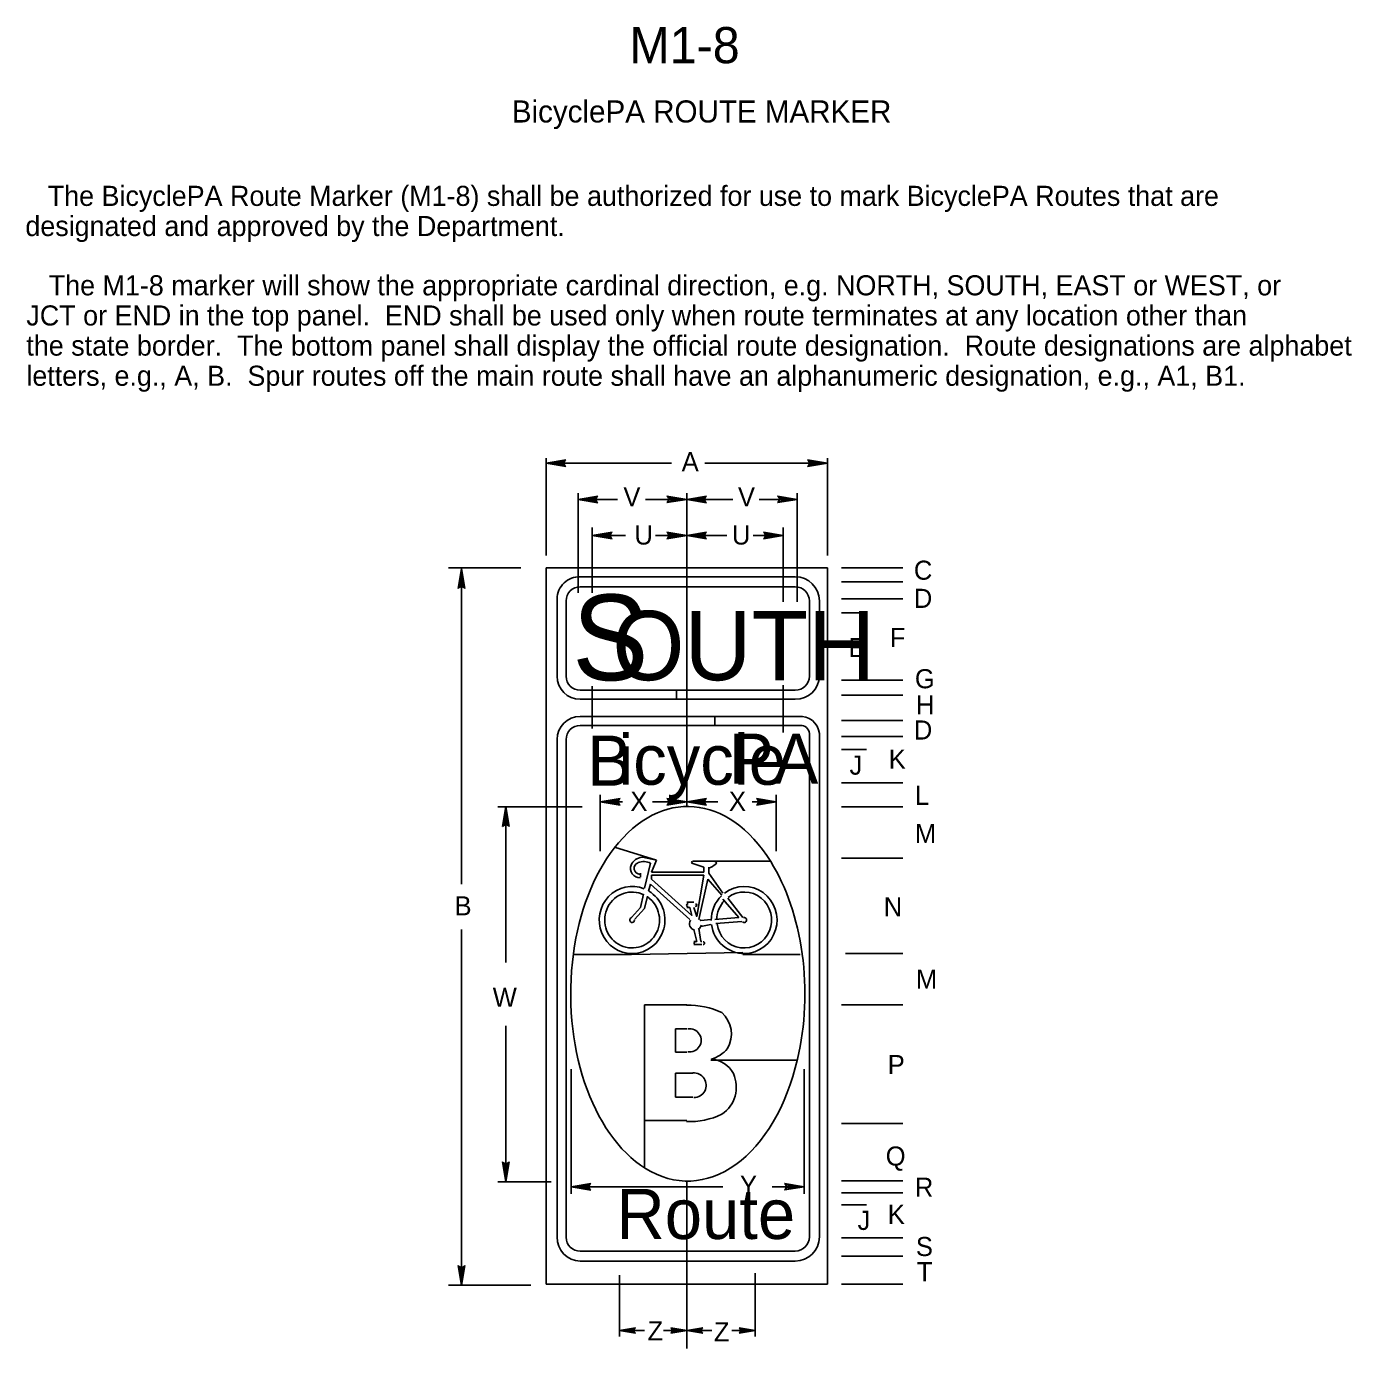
# Model space of a CAD drawing. Extents: x 0.013 to 0.192, y 0.004 to 0.259.
# Drawn here: x 0.0274 to 0.1922, y 0.0948 to 0.2592 of the extents above; entities that cross this region are included whole.
import ezdxf

# ---------------------------------------------------------------- set-up
doc = ezdxf.new("R2010")
doc.units = 0
for name, color, linetype in [('1', 7, 'Continuous'), ('2', 7, 'Continuous'), ('3', 7, 'Continuous')]:
    doc.layers.add(name, color=color, linetype=linetype)

# ---------------------------------------------------------------- blocks, each defined once
blk = doc.blocks.new('RARROW')
at = {"layer": '3'}
for p, q in [((-2.156, 0.28500000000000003), (-2.2665, 0.384625)), ((-2.2665, 0.384625), (0, 0)), ((0, 0), (-2.2665, -0.379125)), ((-2.156, 0.28500000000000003), (-2.075625, 0.12075)), ((0, 0), (-2.156, 0.28500000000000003)), ((-2.14975, -0.2705), (0, 0)), ((-2.075625, 0.12075), (0, 0)), ((0, 0), (-2.074, -0.108)), ((-2.2665, -0.379125), (-2.14975, -0.2705)), ((-2.074, -0.108), (-2.14975, -0.2705))]:
    blk.add_line(p, q, dxfattribs=at)

msp = doc.modelspace()

# ---------------------------------------------------------------- linework, layer by layer
at = {"layer": '3'}
for p, q in [((0.092, 0.193375), (0.092, 0.20550000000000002)), ((0.092, 0.204875), (0.107625, 0.204875)), ((0.11175, 0.204875), (0.127, 0.204875)), ((0.127, 0.193375), (0.127, 0.20550000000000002)), ((0.096, 0.18875), (0.096, 0.201125)), ((0.1095, 0.19425), (0.1095, 0.201125)), ((0.12325, 0.18762500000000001), (0.12325, 0.201125)), ((0.096, 0.200375), (0.100875, 0.200375)), ((0.104375, 0.200375), (0.1095, 0.200375)), ((0.1095, 0.200375), (0.11525, 0.200375)), ((0.11850000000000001, 0.200375), (0.12325, 0.200375)), ((0.09775, 0.18875), (0.09775, 0.196875)), ((0.1215, 0.18762500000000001), (0.1215, 0.196875)), ((0.09775, 0.195875), (0.10187500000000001, 0.195875)), ((0.105625, 0.195875), (0.1095, 0.195875)), ((0.1095, 0.195875), (0.1145, 0.195875)), ((0.11775000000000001, 0.195875), (0.1215, 0.195875)), ((0.1095, 0.162125), (0.1095, 0.19425)), ((0.088875, 0.19187500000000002), (0.079875, 0.19187500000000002)), ((0.0815, 0.1525), (0.0815, 0.19187500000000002)), ((0.127, 0.19187500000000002), (0.092, 0.19187500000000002)), ((0.092, 0.19187500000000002), (0.092, 0.10275000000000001)), ((0.127, 0.19187500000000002), (0.127, 0.10275000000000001)), ((0.12875, 0.19187500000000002), (0.136375, 0.19187500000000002)), ((0.123, 0.19075), (0.09625, 0.19075)), ((0.12875, 0.19012500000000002), (0.136375, 0.19012500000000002)), ((0.093375, 0.188), (0.093375, 0.178375)), ((0.09625, 0.1895), (0.123, 0.1895)), ((0.12875, 0.188), (0.136375, 0.188)), ((0.0945, 0.178375), (0.0945, 0.18775)), ((0.12475, 0.18775), (0.12475, 0.178375)), ((0.126, 0.178375), (0.126, 0.18775)), ((0.12875, 0.18625), (0.131875, 0.18625)), ((0.09775, 0.171875), (0.09775, 0.177125)), ((0.1215, 0.171375), (0.1215, 0.17725)), ((0.12875, 0.177875), (0.136375, 0.177875)), ((0.12875, 0.176), (0.136375, 0.176)), ((0.09625, 0.173375), (0.113, 0.173375)), ((0.12875, 0.172875), (0.136375, 0.172875)), ((0.093375, 0.108625), (0.093375, 0.1705)), ((0.0945, 0.1705), (0.0945, 0.108625)), ((0.12475, 0.108625), (0.12475, 0.17125)), ((0.126, 0.17125), (0.126, 0.108625)), ((0.12875, 0.170875), (0.136375, 0.170875)), ((0.12875, 0.16925), (0.131875, 0.16925)), ((0.12875, 0.165125), (0.136375, 0.165125)), ((0.09875, 0.15662500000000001), (0.09875, 0.163625)), ((0.120625, 0.15662500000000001), (0.120625, 0.163625)), ((0.08600000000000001, 0.162125), (0.0965, 0.162125)), ((0.08700000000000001, 0.14275000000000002), (0.08700000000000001, 0.162125)), ((0.09875, 0.16275), (0.1015, 0.16275)), ((0.10525, 0.16275), (0.1095, 0.16275)), ((0.113375, 0.16275), (0.1095, 0.16275)), ((0.120625, 0.16275), (0.11762500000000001, 0.16275)), ((0.12875, 0.162125), (0.136375, 0.162125)), ((0.10575, 0.1555), (0.1005, 0.15712500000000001)), ((0.1005, 0.15712500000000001), (0.10575, 0.1555)), ((0.1005, 0.15712500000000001), (0.1005, 0.15712500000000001)), ((0.104625, 0.15575), (0.10400000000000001, 0.155875)), ((0.10400000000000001, 0.155875), (0.10575, 0.1555)), ((0.105, 0.155125), (0.10425, 0.152)), ((0.105125, 0.154), (0.10575, 0.1555)), ((0.110125, 0.155125), (0.111625, 0.154625)), ((0.113, 0.155375), (0.11025, 0.155375)), ((0.113, 0.155375), (0.113, 0.155375)), ((0.113, 0.155375), (0.113, 0.155375)), ((0.12, 0.155375), (0.113, 0.155375)), ((0.12, 0.155375), (0.113, 0.155375)), ((0.12875, 0.15575), (0.136375, 0.15575)), ((0.10375000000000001, 0.153375), (0.10375000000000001, 0.153875)), ((0.111625, 0.154), (0.105125, 0.154)), ((0.111625, 0.154625), (0.111625, 0.154)), ((0.11225, 0.154625), (0.11225, 0.153875)), ((0.11225, 0.153875), (0.114, 0.151375)), ((0.105, 0.1525), (0.10475, 0.151625)), ((0.109875, 0.148125), (0.105, 0.1525)), ((0.112125, 0.153125), (0.111, 0.148125)), ((0.113875, 0.151125), (0.112125, 0.153125)), ((0.104125, 0.15125), (0.10375000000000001, 0.149625)), ((0.10425, 0.1495), (0.104625, 0.151)), ((0.104625, 0.151), (0.104625, 0.151)), ((0.110375, 0.15025), (0.1095, 0.15025)), ((0.113875, 0.151125), (0.113875, 0.151125)), ((0.116, 0.148375), (0.114, 0.150625)), ((0.114625, 0.15075), (0.114625, 0.15075)), ((0.114625, 0.15075), (0.1165, 0.148375)), ((0.10375000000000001, 0.149625), (0.10262500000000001, 0.148375)), ((0.10300000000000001, 0.148125), (0.10425, 0.1495)), ((0.113, 0.148125), (0.116, 0.148375)), ((0.0815, 0.10275000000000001), (0.0815, 0.146875)), ((0.109875, 0.148125), (0.109875, 0.148125)), ((0.11075, 0.145375), (0.110375, 0.146875)), ((0.111, 0.147), (0.11125, 0.145375)), ((0.11125, 0.148), (0.1125, 0.148125)), ((0.1125, 0.1475), (0.11125, 0.14725)), ((0.116375, 0.147875), (0.113125, 0.147625)), ((0.113125, 0.147625), (0.113125, 0.147625)), ((0.110375, 0.145375), (0.11075, 0.145375)), ((0.11125, 0.145375), (0.111375, 0.145375)), ((0.10262500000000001, 0.14375000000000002), (0.095375, 0.14375000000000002)), ((0.095375, 0.14375000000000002), (0.10262500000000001, 0.14375000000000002)), ((0.095375, 0.14375000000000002), (0.095375, 0.14375000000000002)), ((0.10262500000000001, 0.14375000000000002), (0.1165, 0.14400000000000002)), ((0.10262500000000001, 0.14375000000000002), (0.1165, 0.14400000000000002)), ((0.111375, 0.145), (0.110375, 0.145)), ((0.1165, 0.14375000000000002), (0.123625, 0.14375000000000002)), ((0.1165, 0.14375000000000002), (0.123625, 0.14375000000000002)), ((0.12925, 0.143875), (0.136375, 0.143875)), ((0.1095, 0.1375), (0.10425, 0.1375)), ((0.10425, 0.1375), (0.10425, 0.11725000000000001)), ((0.12875, 0.1375), (0.136375, 0.1375)), ((0.08700000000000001, 0.115625), (0.08700000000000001, 0.134875)), ((0.108125, 0.131625), (0.108125, 0.1345)), ((0.108125, 0.1345), (0.1095, 0.1345)), ((0.1095, 0.131625), (0.108125, 0.131625)), ((0.12325, 0.130625), (0.1125, 0.130625)), ((0.123, 0.130625), (0.1125, 0.130625)), ((0.12325, 0.130625), (0.123, 0.130625)), ((0.095125, 0.114), (0.095125, 0.1295)), ((0.108125, 0.129), (0.11025, 0.129)), ((0.108125, 0.126), (0.108125, 0.129)), ((0.124125, 0.114), (0.124125, 0.1295)), ((0.11025, 0.126), (0.108125, 0.126)), ((0.1095, 0.123125), (0.10425, 0.123125)), ((0.10425, 0.123125), (0.10425, 0.11725000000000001)), ((0.12875, 0.12275), (0.136375, 0.12275)), ((0.08600000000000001, 0.1155), (0.092625, 0.1155)), ((0.1095, 0.09475), (0.1095, 0.115625)), ((0.12875, 0.115625), (0.136375, 0.115625)), ((0.095125, 0.114875), (0.114, 0.114875)), ((0.120125, 0.114875), (0.124125, 0.114875)), ((0.12875, 0.114125), (0.136375, 0.114125)), ((0.12875, 0.112625), (0.131875, 0.112625)), ((0.12875, 0.1085), (0.136375, 0.1085)), ((0.09625, 0.106875), (0.123, 0.106875)), ((0.123, 0.105625), (0.09625, 0.105625)), ((0.12875, 0.10625), (0.136375, 0.10625)), ((0.101125, 0.09625), (0.101125, 0.10387500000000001)), ((0.11800000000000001, 0.09625), (0.11800000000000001, 0.104125)), ((0.090125, 0.10262500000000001), (0.079875, 0.10262500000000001)), ((0.127, 0.10275000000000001), (0.092, 0.10275000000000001)), ((0.12875, 0.10275000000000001), (0.136375, 0.10275000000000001)), ((0.101125, 0.097), (0.10425, 0.097)), ((0.106625, 0.097), (0.1095, 0.097)), ((0.1095, 0.097), (0.112625, 0.097)), ((0.115125, 0.097), (0.11800000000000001, 0.097))]:
    msp.add_line(p, q, dxfattribs=at)
for points in [[(0.09625, 0.17550000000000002), (0.10825, 0.17550000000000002), (0.10825, 0.176625), (0.09625, 0.176625)], [(0.123, 0.176625), (0.10825, 0.176625), (0.10825, 0.17550000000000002), (0.123, 0.17550000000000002)], [(0.113, 0.173375), (0.113, 0.17225000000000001), (0.09625, 0.17225000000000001)], [(0.123625, 0.17225000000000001), (0.113, 0.17225000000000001), (0.113, 0.173375), (0.123375, 0.173375)], [(0.1095, 0.149625), (0.109875, 0.149625), (0.110125, 0.148625), (0.105125, 0.153125), (0.105125, 0.153625), (0.111625, 0.153625)], [(0.111625, 0.153625), (0.11075, 0.1485), (0.110375, 0.149625), (0.110375, 0.149625)]]:
    msp.add_lwpolyline(points, dxfattribs=at)
for centre, radius, start, end in [((0.09618083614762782, 0.18794446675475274), 0.002806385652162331, 88.58779166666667, 178.86614722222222), ((0.12300000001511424, 0.18775000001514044), 0.002999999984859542, 0, 90), ((0.09624999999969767, 0.1877500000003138), 0.0017499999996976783, 90, 180), ((0.12300000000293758, 0.1877500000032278), 0.0017499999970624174, 0, 90), ((0.09624999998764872, 0.1783749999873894), 0.002874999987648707, 180, 270), ((0.09624999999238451, 0.1783749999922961), 0.0017499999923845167, 180, 270), ((0.12299999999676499, 0.17837500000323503), 0.0017500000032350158, 270, 0), ((0.12306250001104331, 0.1784374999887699), 0.002938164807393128, 268.78112500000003, 358.78112500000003), ((0.09625000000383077, 0.17049999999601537), 0.0028750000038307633, 90, 180), ((0.12362500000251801, 0.1710000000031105), 0.002388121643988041, 6.009005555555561, 96.00900555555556), ((0.09625000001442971, 0.17049999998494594), 0.0017500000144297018, 90, 180), ((0.12368750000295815, 0.1711875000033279), 0.0010643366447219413, 3.366461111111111, 93.36646111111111), ((0.10404730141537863, 0.15425182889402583), 0.0015972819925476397, 93.5801888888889, 156.6766), ((0.10372970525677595, 0.15448047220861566), 0.0007575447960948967, 112.33130277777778, 268.05661388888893), ((0.1041421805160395, 0.15356406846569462), 0.001756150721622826, 60.59737777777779, 112.67573055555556), ((0.10366965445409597, 0.1544696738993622), 0.0011653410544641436, 159.16154444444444, 272.64576666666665), ((0.10976705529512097, 0.12778106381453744), 0.00966476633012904, 64.91580277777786, 91.7117472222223), ((0.11145229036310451, 0.1338557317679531), 0.0036046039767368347, 329.89579722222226, 47.99597777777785), ((0.10986700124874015, 0.13308092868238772), 0.0014274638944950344, 261.5001972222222, 98.49980277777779), ((0.11127861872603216, 0.13490674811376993), 0.004360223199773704, 287.0058444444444, 319.02734722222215), ((0.11233826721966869, 0.1274018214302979), 0.0033423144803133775, 27.545941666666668, 86.30179444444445), ((0.11039280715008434, 0.12749953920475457), 0.001528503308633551, 270.00161944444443, 95.1911), ((0.11159194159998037, 0.12726206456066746), 0.004074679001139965, 303.89755, 24.43358055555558), ((0.10976705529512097, 0.13263317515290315), 0.009664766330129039, 268.2882527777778, 295.08419722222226), ((0.09631250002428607, 0.10856250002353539), 0.002938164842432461, 178.78112500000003, 268.78112500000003), ((0.09622435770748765, 0.1086111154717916), 0.0017363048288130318, 180.84619166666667, 270.84619166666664), ((0.12300000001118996, 0.1086249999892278), 0.0017499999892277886, 270, 0), ((0.12300000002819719, 0.10862499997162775), 0.0029999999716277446, 270, 0)]:
    msp.add_arc(centre, radius, start, end, dxfattribs=at)
for centre, major_axis, ratio, start_param, end_param in [((0.10963271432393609, 0.1388744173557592), (1.4266637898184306e-18, 0.0232991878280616), 0.6249999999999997, 5.495524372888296, 6.964212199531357), ((0.10963271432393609, 0.1388744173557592), (1.4266637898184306e-18, 0.0232991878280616), 0.6249999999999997, 0.6810429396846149, 1.3549990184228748), ((0.11022207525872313, 0.15520128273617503), (6.81501369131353e-21, 0.00011129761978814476), 0.9804052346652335, 0, 2.7964537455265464), ((0.11078883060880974, 0.15808036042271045), (-7.139456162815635e-19, -0.0038865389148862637), 0.9804052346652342, 0.3922214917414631, 0.6561810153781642), ((0.11303251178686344, 0.1551456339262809), (-3.0667561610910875e-20, -0.0001669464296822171), 0.9804052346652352, 0.5182421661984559, 3.141592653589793), ((0.10963271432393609, 0.1388744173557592), (1.4266637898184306e-18, 0.0232991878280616), 0.6249999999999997, 4.927689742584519, 5.4955178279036), ((0.10270776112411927, 0.14805041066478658), (2.5556301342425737e-19, 0.004173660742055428), 0.980405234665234, 5.90428067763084, 9.426492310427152), ((0.10270776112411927, 0.14805041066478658), (2.1296917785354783e-19, 0.003478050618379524), 0.9804052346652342, 5.8372009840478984, 11.962836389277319), ((0.10270776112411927, 0.14805041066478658), (2.5556301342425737e-19, 0.004173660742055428), 0.980405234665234, 3.1432242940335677, 5.749303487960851), ((0.11664618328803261, 0.14805041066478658), (2.1296917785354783e-19, 0.003478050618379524), 0.9804052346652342, 1.7079627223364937, 6.913561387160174), ((0.11664618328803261, 0.14805041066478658), (2.5556301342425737e-19, 0.004173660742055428), 0.980405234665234, 3.1582208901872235, 6.92157007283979), ((0.10965005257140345, 0.14989595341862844), (1.0686641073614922e-20, 0.00017452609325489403), 0.980405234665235, 6.198627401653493, 9.509335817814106), ((0.11058632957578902, 0.14990614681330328), (1.0686641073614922e-20, 0.00017452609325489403), 0.980405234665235, 3.057034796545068, 6.187256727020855), ((0.11664618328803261, 0.14805041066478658), (2.5556301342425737e-19, 0.004173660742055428), 0.980405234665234, 0.7638517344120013, 1.583042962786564), ((0.11664618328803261, 0.14805041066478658), (2.1296917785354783e-19, 0.003478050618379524), 0.9804052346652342, 0.7848713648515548, 1.5684358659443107), ((0.10270776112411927, 0.14805041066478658), (1.8826475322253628e-20, 0.0003074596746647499), 0.9804052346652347, 0.2825696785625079, 4.644742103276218), ((0.11664618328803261, 0.14805041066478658), (1.8826475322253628e-20, 0.0003074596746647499), 0.9804052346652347, 2.3681356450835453, 6.55357316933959), ((0.11058611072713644, 0.14758991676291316), (4.7130035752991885e-20, 0.0007696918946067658), 0.9804052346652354, 0.9898988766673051, 3.006996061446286), ((0.11058611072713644, 0.14758991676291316), (4.7130035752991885e-20, 0.0007696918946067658), 0.9804052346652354, 3.623585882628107, 4.496485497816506), ((0.11058611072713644, 0.14758991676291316), (4.7130035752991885e-20, 0.0007696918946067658), 0.9804052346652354, 5.179197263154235, 5.449443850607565), ((0.11664618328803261, 0.14805041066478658), (2.5556301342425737e-19, 0.004173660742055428), 0.980405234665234, 1.7006056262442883, 3.158212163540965), ((0.11058529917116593, 0.14517754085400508), (1.0686641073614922e-20, 0.00017452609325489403), 0.980405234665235, 6.198627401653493, 9.509335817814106), ((0.11154778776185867, 0.14517754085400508), (1.0686641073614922e-20, 0.00017452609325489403), 0.980405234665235, 3.0570347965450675, 6.36774321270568), ((0.10963271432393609, 0.1388744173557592), (1.4266637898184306e-18, 0.0232991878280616), 0.6249999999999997, 1.3561330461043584, 2.77126399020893), ((0.10963271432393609, 0.1388744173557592), (1.4266637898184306e-18, 0.0232991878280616), 0.6249999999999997, 4.355608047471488, 4.9260615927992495), ((0.10963271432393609, 0.1388744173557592), (1.4266637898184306e-18, 0.0232991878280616), 0.6249999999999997, 2.771276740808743, 4.3556411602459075)]:
    msp.add_ellipse(centre, major_axis=major_axis, ratio=ratio, start_param=start_param, end_param=end_param, dxfattribs=at)

# ---------------------------------------------------------------- block references
for p, xscale, yscale, rotation in [((0.092, 0.204875), 0.0010855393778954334, 0.0010738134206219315, 180), ((0.096, 0.200375), 0.0010855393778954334, 0.0010738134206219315, 180), ((0.1095, 0.200375), 0.0010855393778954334, 0.0010738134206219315, 180), ((0.09775, 0.195875), 0.0010855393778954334, 0.0010738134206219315, 180), ((0.1095, 0.195875), 0.0010855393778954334, 0.0010738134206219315, 180), ((0.0815, 0.19175), 0.0010855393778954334, 0.0010738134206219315, 90), ((0.09875, 0.16275), 0.0010855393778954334, 0.0010738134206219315, 180), ((0.1095, 0.16275), 0.0010855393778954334, 0.0010738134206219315, 180), ((0.08700000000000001, 0.162125), 0.0010855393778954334, 0.0010738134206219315, 90), ((0.08700000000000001, 0.1155), 0.0010855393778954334, 0.0010738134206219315, -90.00000000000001), ((0.095125, 0.114875), 0.0010855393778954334, 0.0010738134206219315, 180), ((0.0815, 0.10262500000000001), 0.0010855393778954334, 0.0010738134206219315, -90.00000000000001), ((0.101125, 0.097), 0.0008792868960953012, 0.0008697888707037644, 180), ((0.1095, 0.097), 0.0008792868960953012, 0.0008697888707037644, 180)]:
    msp.add_blockref('RARROW', p, dxfattribs=dict(at, xscale=xscale, yscale=yscale, rotation=rotation))
for p, xscale, yscale in [((0.127, 0.204875), 0.0010855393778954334, 0.0010738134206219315), ((0.1095, 0.200375), 0.0010855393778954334, 0.0010738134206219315), ((0.12325, 0.200375), 0.0010855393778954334, 0.0010738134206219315), ((0.1095, 0.195875), 0.0010855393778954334, 0.0010738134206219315), ((0.1215, 0.195875), 0.0010855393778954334, 0.0010738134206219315), ((0.1095, 0.16275), 0.0010855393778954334, 0.0010738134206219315), ((0.120625, 0.16275), 0.0010855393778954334, 0.0010738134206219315), ((0.124125, 0.114875), 0.0010855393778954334, 0.0010738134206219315), ((0.1095, 0.097), 0.0008792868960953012, -0.0008697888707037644), ((0.11800000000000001, 0.097), 0.0008792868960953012, -0.0008697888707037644)]:
    msp.add_blockref('RARROW', p, dxfattribs=dict(at, xscale=xscale, yscale=yscale))

# ---------------------------------------------------------------- texts
at = {"layer": '1'}
for s, height, p in [('M1-8', 0.0045000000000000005, (0.10237500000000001, 0.254625)), ('BicyclePA ROUTE MARKER', 0.00275025, (0.08775000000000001, 0.24725))]:
    msp.add_text(s, height=height, dxfattribs=at).set_placement(p)
at = {"layer": '2'}
for s, p in [('   The BicyclePA Route Marker (M1-8) shall be authorized for use to mark BicyclePA Routes that are', (0.02725, 0.236875)), ('designated and approved by the Department.', (0.02725, 0.233125)), ('   The M1-8 marker will show the appropriate cardinal direction, e.g. NORTH, SOUTH, EAST or WEST, or', (0.027375, 0.22574975)), ('JCT or END in the top panel.  END shall be used only when route terminates at any location other than', (0.027375, 0.222)), ('the state border.  The bottom panel shall display the official route designation.  Route designations are alphabet', (0.027375, 0.21825025)), ('letters, e.g., A, B.  Spur routes off the main route shall have an alphanumeric designation, e.g., A1, B1.', (0.027375, 0.21450049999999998))]:
    msp.add_text(s, height=0.0024997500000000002, dxfattribs=at).set_placement(p)
at = {"layer": '3'}
for s, height, p in [('A', 0.0023752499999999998, (0.108875, 0.203875)), ('V', 0.0023752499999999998, (0.10162500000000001, 0.1995)), ('V', 0.0023752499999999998, (0.115875, 0.1995)), ('U', 0.0023752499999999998, (0.10300000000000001, 0.19475)), ('U', 0.0023752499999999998, (0.115125, 0.19475)), ('C', 0.0023752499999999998, (0.13775, 0.19037500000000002)), ('S', 0.01065225, (0.09525, 0.177875)), ('D', 0.0023752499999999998, (0.13775, 0.186875)), ('OUTH', 0.00862725, (0.10025, 0.177875)), ('E', 0.0023752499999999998, (0.129625, 0.18075)), ('F', 0.0023752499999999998, (0.13475, 0.182)), ('G', 0.0023752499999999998, (0.137875, 0.176875)), ('H', 0.0023752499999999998, (0.138, 0.173625)), ('icycle', 0.00623325, (0.101, 0.164875)), ('D', 0.0023752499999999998, (0.13775, 0.1705)), ('B', 0.0062325, (0.097125, 0.16475)), ('PA', 0.00623325, (0.11475, 0.165)), ('J', 0.0023752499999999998, (0.12975, 0.166125)), ('K', 0.0023752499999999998, (0.134625, 0.166875)), ('X', 0.0023752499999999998, (0.10250000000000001, 0.161625)), ('X', 0.0023752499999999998, (0.11475, 0.161625)), ('L', 0.0023752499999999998, (0.137875, 0.162375)), ('M', 0.0023752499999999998, (0.137875, 0.15762500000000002)), ('B', 0.0023752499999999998, (0.080625, 0.148625)), ('N', 0.0023752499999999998, (0.134, 0.1485)), ('M', 0.0023752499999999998, (0.138, 0.1395)), ('W', 0.0023752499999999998, (0.085375, 0.13725)), ('P', 0.0023752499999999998, (0.1345, 0.128875)), ('Q', 0.0023752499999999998, (0.13425, 0.11750000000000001)), ('Y', 0.0023752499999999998, (0.116125, 0.113875)), ('R', 0.0023752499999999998, (0.137875, 0.113625)), ('Route', 0.00623325, (0.10075, 0.108375)), ('K', 0.0023752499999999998, (0.1345, 0.11025)), ('J', 0.0023752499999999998, (0.13075, 0.1095)), ('S', 0.0023752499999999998, (0.138, 0.10625)), ('T', 0.0023752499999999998, (0.138125, 0.10312500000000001)), ('Z', 0.0023752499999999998, (0.104625, 0.09575)), ('Z', 0.0023752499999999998, (0.112875, 0.095625))]:
    msp.add_text(s, height=height, dxfattribs=at).set_placement(p)

doc.saveas('drawing.dxf')
